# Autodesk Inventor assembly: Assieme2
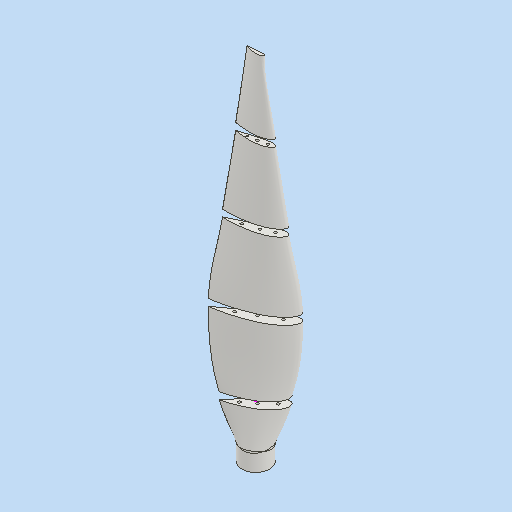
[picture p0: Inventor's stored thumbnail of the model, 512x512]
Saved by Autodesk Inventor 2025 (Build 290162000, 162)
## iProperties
Created: 2025-02
Part Number: Assieme2
Document SubType Name: Assembly
Designer: Ryzen5700u
Author: Ryzen5700u
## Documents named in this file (6)
- C:\Users\Ryzen5700u\Desktop\eolico orizzontale\Assieme2.iam
- C:\Users\Ryzen5700u\Desktop\eolico orizzontale\aolico naca_200mm_A.ipt
- C:\Users\Ryzen5700u\Desktop\eolico orizzontale\aolico naca_200mm_B.ipt
- C:\Users\Ryzen5700u\Desktop\eolico orizzontale\aolico naca_200mm_C.ipt
- C:\Users\Ryzen5700u\Desktop\eolico orizzontale\aolico naca_200mm_D.ipt
- C:\Users\Ryzen5700u\Desktop\eolico orizzontale\aolico naca_200mm_E.ipt
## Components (5 placed, 5 different names)
1. aolico naca_200mm_A:1 — Coincidente:1, Allineato:1, Allineato:2, Allineato:3, Allineato:4, Allineato:5, Allineato:6, Allineato:7, Allineato:8
2. aolico naca_200mm_B:1 — Coincidente:1, Coincidente:2, Allineato:1, Allineato:2
3. aolico naca_200mm_C:1 — Coincidente:2, Coincidente:3, Allineato:3, Allineato:4
4. aolico naca_200mm_D:1 — Coincidente:3, Coincidente:4, Allineato:5, Allineato:6
5. aolico naca_200mm_E:1 — Coincidente:4, Allineato:7, Allineato:8
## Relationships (12: Flush 8, Mate 4)
- Coincidente:1 [Mate]: aolico naca_200mm_A:1 ↔ aolico naca_200mm_B:1
- Coincidente:2 [Mate]: aolico naca_200mm_B:1 ↔ aolico naca_200mm_C:1
- Coincidente:3 [Mate]: aolico naca_200mm_C:1 ↔ aolico naca_200mm_D:1
- Coincidente:4 [Mate]: aolico naca_200mm_D:1 ↔ aolico naca_200mm_E:1
- Allineato:1 [Flush]: aolico naca_200mm_A:1 ↔ aolico naca_200mm_B:1
- Allineato:2 [Flush]: aolico naca_200mm_A:1 ↔ aolico naca_200mm_B:1
- Allineato:3 [Flush]: aolico naca_200mm_A:1 ↔ aolico naca_200mm_C:1
- Allineato:4 [Flush]: aolico naca_200mm_A:1 ↔ aolico naca_200mm_C:1
- Allineato:5 [Flush]: aolico naca_200mm_A:1 ↔ aolico naca_200mm_D:1
- Allineato:6 [Flush]: aolico naca_200mm_A:1 ↔ aolico naca_200mm_D:1
- Allineato:7 [Flush]: aolico naca_200mm_A:1 ↔ aolico naca_200mm_E:1
- Allineato:8 [Flush]: aolico naca_200mm_A:1 ↔ aolico naca_200mm_E:1
